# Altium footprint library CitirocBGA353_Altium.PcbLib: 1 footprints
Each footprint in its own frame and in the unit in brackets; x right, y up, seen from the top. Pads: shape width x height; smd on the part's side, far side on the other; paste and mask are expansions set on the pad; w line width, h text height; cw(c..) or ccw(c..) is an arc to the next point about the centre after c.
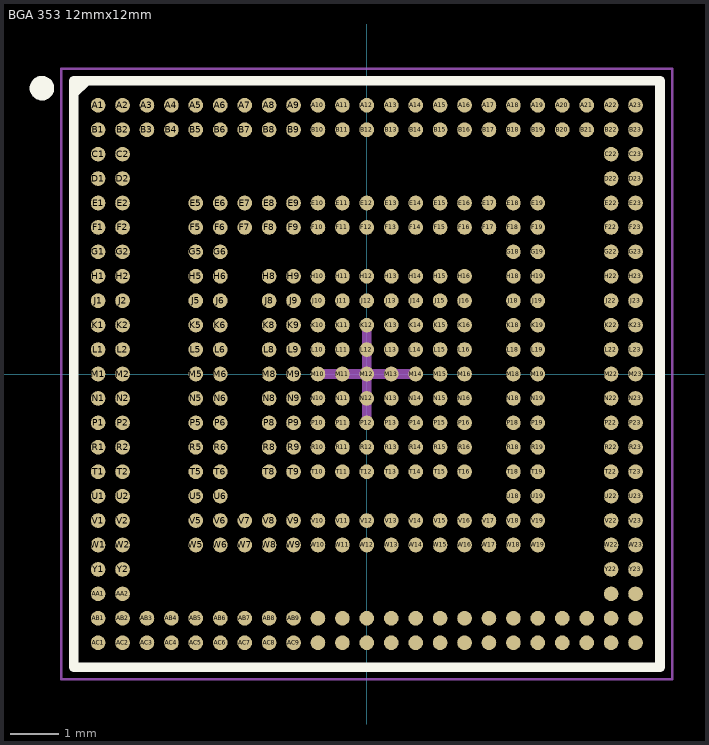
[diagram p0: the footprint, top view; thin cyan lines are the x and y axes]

## BGA 353 12mmx12mm [mm] "BGA, 353-Leads, Body 12,00x12,00mmx1,20mm, Pitch 0,50mm"
height 1.2
pads (353):
  round 0.3 smd: A1(-5.5,5.5) A2(-5,5.5) A3(-4.5,5.5) A4(-4,5.5) A5(-3.5,5.5) A6(-3,5.5) A7(-2.5,5.5) A8(-2,5.5) A9(-1.5,5.5) A10(-1,5.5) A11(-0.5,5.5) A12(0,5.5) A13(0.5,5.5) A14(1,5.5) A15(1.5,5.5) A16(2,5.5) A17(2.5,5.5) A18(3,5.5) A19(3.5,5.5) A20(4,5.5) A21(4.5,5.5) A22(5,5.5) A23(5.5,5.5) AA1(-5.5,-4.5) AA2(-5,-4.5) AA22(5,-4.5) AA23(5.5,-4.5) AB1(-5.5,-5) AB2(-5,-5) AB3(-4.5,-5) AB4(-4,-5) AB5(-3.5,-5) AB6(-3,-5) AB7(-2.5,-5) AB8(-2,-5) AB9(-1.5,-5) AB10(-1,-5) AB11(-0.5,-5) AB12(0,-5) AB13(0.5,-5) AB14(1,-5) AB15(1.5,-5) AB16(2,-5) AB17(2.5,-5) AB18(3,-5) AB19(3.5,-5) AB20(4,-5) AB21(4.5,-5) AB22(5,-5) AB23(5.5,-5) AC1(-5.5,-5.5) AC2(-5,-5.5) AC3(-4.5,-5.5) AC4(-4,-5.5) AC5(-3.5,-5.5) AC6(-3,-5.5) AC7(-2.5,-5.5) AC8(-2,-5.5) AC9(-1.5,-5.5) AC10(-1,-5.5) AC11(-0.5,-5.5) AC12(0,-5.5) AC13(0.5,-5.5) AC14(1,-5.5) AC15(1.5,-5.5) AC16(2,-5.5) AC17(2.5,-5.5) AC18(3,-5.5) AC19(3.5,-5.5) AC20(4,-5.5) AC21(4.5,-5.5) AC22(5,-5.5) AC23(5.5,-5.5) B1(-5.5,5) B2(-5,5) B3(-4.5,5) B4(-4,5) B5(-3.5,5) B6(-3,5) B7(-2.5,5) B8(-2,5) B9(-1.5,5) B10(-1,5) B11(-0.5,5) B12(0,5) B13(0.5,5) B14(1,5) B15(1.5,5) B16(2,5) B17(2.5,5) B18(3,5) B19(3.5,5) B20(4,5) B21(4.5,5) B22(5,5) B23(5.5,5) C1(-5.5,4.5) C2(-5,4.5) C22(5,4.5) C23(5.5,4.5) D1(-5.5,4) D2(-5,4) D22(5,4) D23(5.5,4) E1(-5.5,3.5) E2(-5,3.5) E5(-3.5,3.5) E6(-3,3.5) E7(-2.5,3.5) E8(-2,3.5) E9(-1.5,3.5) E10(-1,3.5) E11(-0.5,3.5) E12(0,3.5) E13(0.5,3.5) E14(1,3.5) E15(1.5,3.5) E16(2,3.5) E17(2.5,3.5) E18(3,3.5) E19(3.5,3.5) E22(5,3.5) E23(5.5,3.5) F1(-5.5,3) F2(-5,3) F5(-3.5,3) F6(-3,3) F7(-2.5,3) F8(-2,3) F9(-1.5,3) F10(-1,3) F11(-0.5,3) F12(0,3) F13(0.5,3) F14(1,3) F15(1.5,3) F16(2,3) F17(2.5,3) F18(3,3) F19(3.5,3) F22(5,3) F23(5.5,3) G1(-5.5,2.5) G2(-5,2.5) G5(-3.5,2.5) G6(-3,2.5) G18(3,2.5) G19(3.5,2.5) G22(5,2.5) G23(5.5,2.5) H1(-5.5,2) H2(-5,2) H5(-3.5,2) H6(-3,2) H8(-2,2) H9(-1.5,2) H10(-1,2) H11(-0.5,2) H12(0,2) H13(0.5,2) H14(1,2) H15(1.5,2) H16(2,2) H18(3,2) H19(3.5,2) H22(5,2) H23(5.5,2) J1(-5.5,1.5) J2(-5,1.5) J5(-3.5,1.5) J6(-3,1.5) J8(-2,1.5) J9(-1.5,1.5) J10(-1,1.5) J11(-0.5,1.5) J12(0,1.5) J13(0.5,1.5) J14(1,1.5) J15(1.5,1.5) J16(2,1.5) J18(3,1.5) J19(3.5,1.5) J22(5,1.5) J23(5.5,1.5) K1(-5.5,1) K2(-5,1) K5(-3.5,1) K6(-3,1) K8(-2,1) K9(-1.5,1) K10(-1,1) K11(-0.5,1) K12(0,1) K13(0.5,1) K14(1,1) K15(1.5,1) K16(2,1) K18(3,1) K19(3.5,1) K22(5,1) K23(5.5,1) L1(-5.5,0.5) L2(-5,0.5) L5(-3.5,0.5) L6(-3,0.5) L8(-2,0.5) L9(-1.5,0.5) L10(-1,0.5) L11(-0.5,0.5) L12(0,0.5) L13(0.5,0.5) L14(1,0.5) L15(1.5,0.5) L16(2,0.5) L18(3,0.5) L19(3.5,0.5) L22(5,0.5) L23(5.5,0.5) M1(-5.5,0) M2(-5,0) M5(-3.5,0) M6(-3,0) M8(-2,0) M9(-1.5,0) M10(-1,0) M11(-0.5,0) M12(0,0) M13(0.5,0) M14(1,0) M15(1.5,0) M16(2,0) M18(3,0) M19(3.5,0) M22(5,0) M23(5.5,0) N1(-5.5,-0.5) N2(-5,-0.5) N5(-3.5,-0.5) N6(-3,-0.5) N8(-2,-0.5) N9(-1.5,-0.5) N10(-1,-0.5) N11(-0.5,-0.5) N12(0,-0.5) N13(0.5,-0.5) N14(1,-0.5) N15(1.5,-0.5) N16(2,-0.5) N18(3,-0.5) N19(3.5,-0.5) N22(5,-0.5) N23(5.5,-0.5) P1(-5.5,-1) P2(-5,-1) P5(-3.5,-1) P6(-3,-1) P8(-2,-1) P9(-1.5,-1) P10(-1,-1) P11(-0.5,-1) P12(0,-1) P13(0.5,-1) P14(1,-1) P15(1.5,-1) P16(2,-1) P18(3,-1) P19(3.5,-1) P22(5,-1) P23(5.5,-1) R1(-5.5,-1.5) R2(-5,-1.5) R5(-3.5,-1.5) R6(-3,-1.5) R8(-2,-1.5) R9(-1.5,-1.5) R10(-1,-1.5) R11(-0.5,-1.5) R12(0,-1.5) R13(0.5,-1.5) R14(1,-1.5) R15(1.5,-1.5) R16(2,-1.5) R18(3,-1.5) R19(3.5,-1.5) R22(5,-1.5) R23(5.5,-1.5) T1(-5.5,-2) T2(-5,-2) T5(-3.5,-2) T6(-3,-2) T8(-2,-2) T9(-1.5,-2) T10(-1,-2) T11(-0.5,-2) T12(0,-2) T13(0.5,-2) T14(1,-2) T15(1.5,-2) T16(2,-2) T18(3,-2) T19(3.5,-2) T22(5,-2) T23(5.5,-2) U1(-5.5,-2.5) U2(-5,-2.5) U5(-3.5,-2.5) U6(-3,-2.5) U18(3,-2.5) U19(3.5,-2.5) U22(5,-2.5) U23(5.5,-2.5) V1(-5.5,-3) V2(-5,-3) V5(-3.5,-3) V6(-3,-3) V7(-2.5,-3) V8(-2,-3) V9(-1.5,-3) V10(-1,-3) V11(-0.5,-3) V12(0,-3) V13(0.5,-3) V14(1,-3) V15(1.5,-3) V16(2,-3) V17(2.5,-3) V18(3,-3) V19(3.5,-3) V22(5,-3) V23(5.5,-3) W1(-5.5,-3.5) W2(-5,-3.5) W5(-3.5,-3.5) W6(-3,-3.5) W7(-2.5,-3.5) W8(-2,-3.5) W9(-1.5,-3.5) W10(-1,-3.5) W11(-0.5,-3.5) W12(0,-3.5) W13(0.5,-3.5) W14(1,-3.5) W15(1.5,-3.5) W16(2,-3.5) W17(2.5,-3.5) W18(3,-3.5) W19(3.5,-3.5) W22(5,-3.5) W23(5.5,-3.5) Y1(-5.5,-4) Y2(-5,-4) Y22(5,-4) Y23(5.5,-4)
Top Overlay:
  circle w0.25: c-6.65,5.85 r0.125
  region: -5.742,6 -6,5.742 -6,6
  lines w0.2: -6,5.742 -5.742,6 ; -6,-6 6,-6 6,6 -6,6 -6,-6
Mechanical 5:
  lines w0.2: -1,0 1,0 ; 0,-1 0,1
Mechanical 13:
  lines w0.1: -6,-6 6,-6 6,6 -6,6 -6,-6
Mechanical 15:
  lines w0.05: -6.25,-6.25 6.25,-6.25 6.25,6.25 -6.25,6.25 -6.25,-6.25
Mechanical 19:
  text ".Designator" at -7.81,-0.5 h1.5
3D body: height 1.2, standoff 0.15, extent -6,-6 6,6
3D body: height 1.21, standoff 0, extent -5.25,3.75 -3.75,5.25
